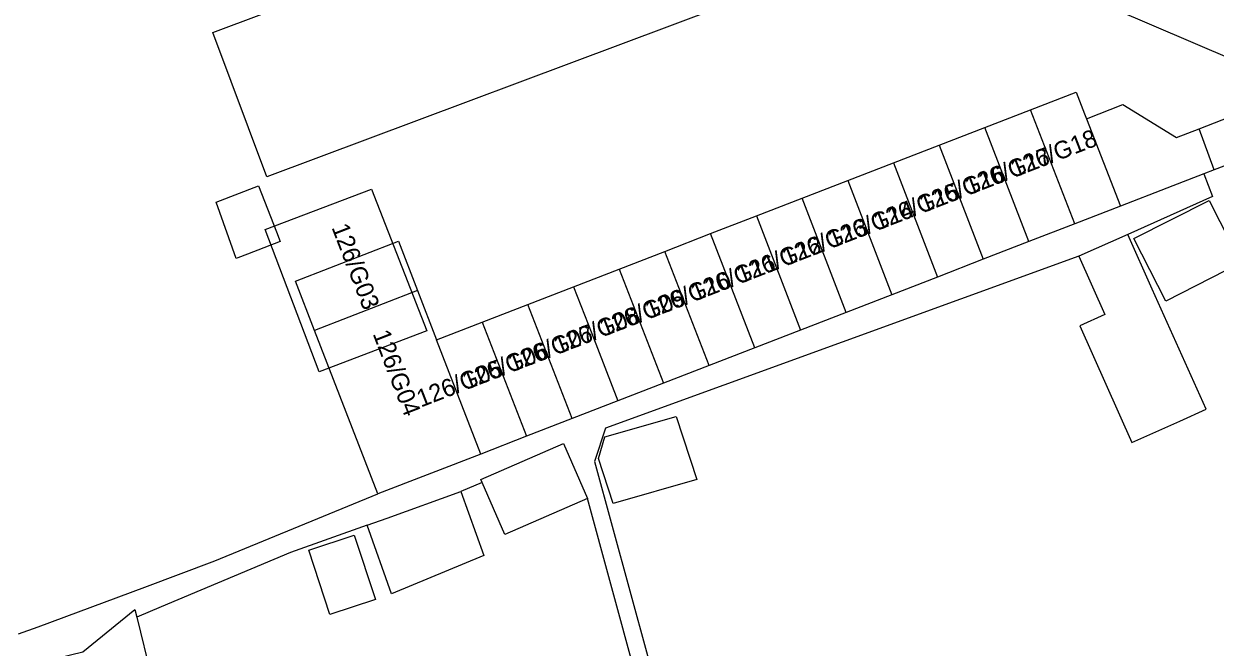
# Model space of a CAD drawing. Extents: x 161801 to 162379, y 382315 to 382832.
# Drawn here: x 162222.7 to 162290.6, y 382535.3 to 382570.8 of the extents above; entities that cross this region are included whole.
import ezdxf

# ---------------------------------------------------------------- set-up
doc = ezdxf.new("R2010")
doc.units = 0
for name, color, linetype in [('IMGEO_Pand', 7, 'Continuous'), ('IMGEO_Pand_nummerreeks', 7, 'Continuous'), ('IMGEO_Pand_vergunning_verleend', 7, 'Continuous'), ('IMGEO_Voetpad_open', 7, 'Continuous')]:
    doc.layers.add(name, color=color, linetype=linetype)

msp = doc.modelspace()

# ---------------------------------------------------------------- linework, layer by layer
at = {"layer": 'IMGEO_Pand'}
for points in [[(162293.943, 382567.792), (162284.769, 382571.71), (162289.23, 382581.835), (162291.245, 382586.514)], [(162289.689, 382564.856), (162293.285, 382566.249), (162293.943, 382567.792)], [(162280.077, 382565.937), (162282.683, 382566.945), (162283.161, 382565.711), (162283.271, 382565.425)], [(162296.196, 382566.83), (162295.097, 382564.25), (162293.759, 382563.738), (162290.559, 382562.512)], [(162283.271, 382565.425), (162285.351, 382566.23), (162288.399, 382564.357), (162289.689, 382564.856)], [(162277.471, 382564.928), (162280.077, 382565.937)], [(162282.596, 382559.43), (162280.077, 382565.937)], [(162283.271, 382565.425), (162285.202, 382560.438)], [(162274.866, 382563.919), (162277.471, 382564.928)], [(162279.99, 382558.421), (162277.471, 382564.928)], [(162290.559, 382562.512), (162289.689, 382564.856)], [(162272.26, 382562.91), (162274.866, 382563.919)], [(162274.866, 382563.919), (162277.385, 382557.412)], [(162269.654, 382561.901), (162272.26, 382562.91)], [(162272.26, 382562.91), (162274.779, 382556.403)], [(162289.964, 382562.282), (162287.854, 382561.465), (162285.202, 382560.438)], [(162290.559, 382562.512), (162289.964, 382562.282)], [(162236.056, 382561.606), (162237.072, 382558.982), (162237.283, 382558.436), (162235.416, 382557.712), (162234.869, 382557.5), (162234.772, 382557.463), (162233.641, 382560.671), (162236.056, 382561.606)], [(162267.048, 382560.893), (162269.654, 382561.901)], [(162269.654, 382561.901), (162272.173, 382555.394)], [(162264.442, 382559.884), (162267.048, 382560.893)], [(162269.567, 382554.386), (162267.048, 382560.893)], [(162287.792, 382555.026), (162285.977, 382558.59), (162290.263, 382560.773), (162292.079, 382557.208), (162287.792, 382555.026)], [(162285.202, 382560.438), (162282.596, 382559.43)], [(162261.837, 382558.875), (162264.442, 382559.884)], [(162264.442, 382559.884), (162266.962, 382553.377)], [(162282.596, 382559.43), (162279.99, 382558.421)], [(162259.231, 382557.866), (162261.837, 382558.875)], [(162264.356, 382552.368), (162261.837, 382558.875)], [(162285.631, 382558.834), (162282.834, 382557.584)], [(162282.834, 382557.584), (162284.317, 382554.266), (162282.892, 382553.629), (162285.865, 382546.979), (162288.586, 382548.196), (162290.086, 382548.867), (162287.025, 382555.715), (162285.631, 382558.834)], [(162239.248, 382553.361), (162238.16, 382556.172), (162244.026, 382558.443), (162245.114, 382555.633)], [(162256.625, 382556.857), (162259.231, 382557.866)], [(162261.75, 382551.359), (162259.231, 382557.866)], [(162279.99, 382558.421), (162277.385, 382557.412)], [(162277.385, 382557.412), (162274.779, 382556.403)], [(162254.019, 382555.849), (162256.625, 382556.857)], [(162256.625, 382556.857), (162259.144, 382550.35)], [(162251.414, 382554.84), (162254.019, 382555.849)], [(162254.019, 382555.849), (162255.052, 382553.181), (162256.539, 382549.342)], [(162274.779, 382556.403), (162272.173, 382555.394)], [(162245.114, 382555.633), (162239.248, 382553.361)], [(162245.114, 382555.633), (162246.202, 382552.822)], [(162272.173, 382555.394), (162269.567, 382554.386)], [(162248.808, 382553.831), (162251.414, 382554.84)], [(162253.933, 382548.333), (162251.414, 382554.84)], [(162246.202, 382552.822), (162248.808, 382553.831)], [(162248.808, 382553.831), (162251.327, 382547.324)], [(162269.567, 382554.386), (162266.962, 382553.377)], [(162242.855, 382544.044), (162239.248, 382553.361)], [(162266.962, 382553.377), (162264.356, 382552.368)], [(162248.721, 382546.315), (162246.202, 382552.822)], [(162264.356, 382552.368), (162261.75, 382551.359)], [(162261.75, 382551.359), (162259.144, 382550.35)], [(162259.144, 382550.35), (162256.539, 382549.342)], [(162256.539, 382549.342), (162253.933, 382548.333)], [(162261.047, 382544.856), (162256.286, 382543.493), (162255.445, 382546.067), (162255.81, 382547.29), (162259.871, 382548.452), (162261.047, 382544.856)], [(162253.933, 382548.333), (162251.327, 382547.324)], [(162251.327, 382547.324), (162248.721, 382546.315)], [(162248.721, 382546.315), (162242.855, 382544.044)], [(162248.8, 382544.69), (162248.799, 382544.693), (162248.725, 382544.864), (162253.441, 382546.916), (162254.806, 382543.779)], [(162254.806, 382543.779), (162250.091, 382541.726), (162248.8, 382544.69)], [(162247.596, 382544.169), (162248.899, 382540.521), (162243.643, 382538.349), (162242.247, 382542.259)], [(162242.247, 382542.259), (162243.388, 382542.667), (162247.596, 382544.169)], [(162238.912, 382540.83), (162241.514, 382541.687), (162242.72, 382538.029), (162240.118, 382537.172), (162238.912, 382540.83)], [(162223.995, 382534.542), (162226.032, 382535.047), (162228.997, 382537.457), (162229.105, 382537.02)], [(162229.105, 382537.02), (162229.934, 382533.677), (162226.637, 382532.859), (162226.915, 382531.736), (162224.948, 382531.248)]]:
    msp.add_lwpolyline(points, dxfattribs=at)
at = {"layer": 'IMGEO_Pand_vergunning_verleend'}
for points in [[(162233.442, 382570.34), (162259.36, 382580.047), (162262.443, 382571.813), (162236.525, 382562.106), (162233.442, 382570.34)], [(162236.425, 382559.108), (162242.497, 382561.416), (162245.659, 382553.337), (162239.508, 382550.998), (162236.425, 382559.108)]]:
    msp.add_lwpolyline(points, dxfattribs=at)
at = {"layer": 'IMGEO_Voetpad_open'}
for points in [[(162289.964, 382562.282), (162290.463, 382560.993), (162285.631, 382558.834)], [(162282.834, 382557.584), (162255.845, 382547.789), (162255.205, 382545.895), (162261.257, 382523.77)], [(162248.8, 382544.69), (162247.596, 382544.169)], [(162222.366, 382536.068), (162223.492, 382536.468), (162229.569, 382538.732), (162233.563, 382540.22), (162242.855, 382544.044)], [(162261.353, 382520.004), (162260.302, 382523.622), (162254.806, 382543.779)], [(162242.247, 382542.259), (162237.871, 382540.697), (162230.495, 382537.603), (162229.105, 382537.02)]]:
    msp.add_lwpolyline(points, dxfattribs=at)

# ---------------------------------------------------------------- texts
at = {"layer": 'IMGEO_Pand_nummerreeks'}
for s, rotation, p in [('126/G18', 21.16353, (162279.187, 382562.075)), ('126/G17', 21.16353, (162276.581, 382561.066)), ('126/G16', 21.16353, (162273.976, 382560.057)), ('126/G15', 21.16353, (162271.37, 382559.048)), ('126/G14', 21.16353, (162268.764, 382558.04)), ('126/G03', 291.16353, (162240.204, 382559.231)), ('126/G13', 21.16353, (162266.158, 382557.031)), ('126/G12', 21.16353, (162263.553, 382556.022)), ('126/G11', 21.16353, (162260.947, 382555.013)), ('126/G10', 21.16353, (162258.341, 382554.004)), ('126/G09', 21.16353, (162255.735, 382552.996)), ('126/G08', 21.16353, (162253.13, 382551.987)), ('126/G04', 291.16353, (162242.552, 382553.167)), ('126/G07', 21.16353, (162250.524, 382550.978)), ('126/G06', 21.16353, (162247.918, 382549.969)), ('126/G05', 21.16353, (162245.312, 382548.96))]:
    msp.add_text(s, height=1, rotation=rotation, dxfattribs=at).set_placement(p)

doc.saveas('drawing.dxf')
